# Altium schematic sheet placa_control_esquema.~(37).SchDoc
size A4
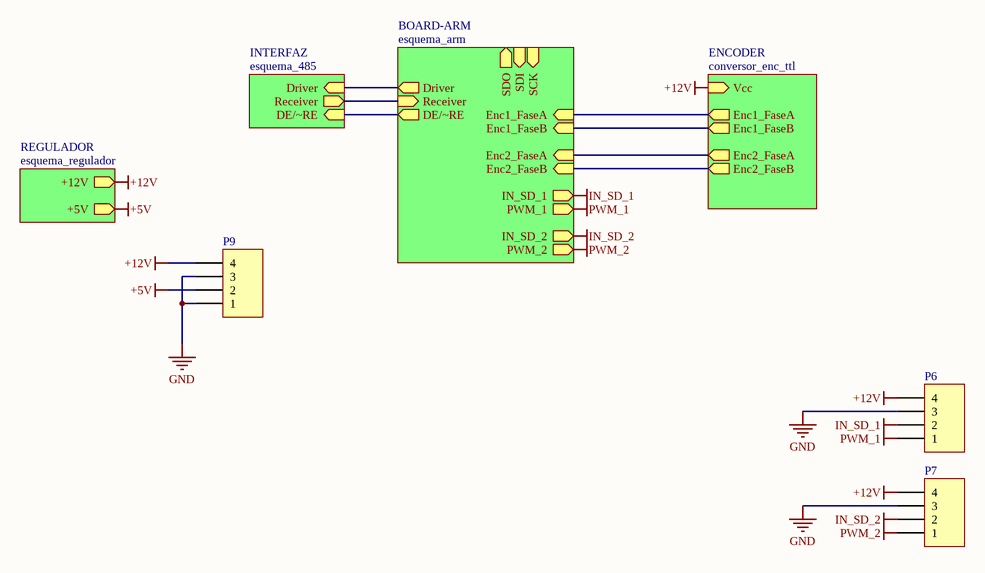
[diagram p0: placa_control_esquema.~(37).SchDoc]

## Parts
P6  Header 4  [HDR1X5]  (value not drawn)
P7  Header 4  [HDR1X5]  (value not drawn)
P9  Header 4  [HDR1X5]  (value not drawn)

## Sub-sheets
BOARD-ARM = esquema_arm: SDI (in), SDO (out), SCK (in), Enc1_FaseA (in), Enc1_FaseB (in), Enc2_FaseA (in), Enc2_FaseB (in), DE/~RE (out), Receiver (in), Driver (out), PWM_1 (out), PWM_2 (out), IN_SD_2 (out), IN_SD_1 (out)
ENCODER = conversor_enc_ttl: Enc1_FaseA (out), Enc1_FaseB (out), Enc2_FaseA (out), Enc2_FaseB (out), Vcc (in)
INTERFAZ = esquema_485: Driver (in), Receiver (out), DE/~RE (in)
REGULADOR = esquema_regulador: +12V (out), +5V (out)

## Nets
+5V: P9.2 ; sheet REGULADOR/+5V
+12V: P6.4 P7.4 P9.4 ; sheet REGULADOR/+12V, sheet ENCODER/Vcc
GND: P6.3 P7.3 P9.1 P9.3
IN_SD_1: P6.2 ; sheet BOARD-ARM/IN_SD_1
IN_SD_2: P7.2 ; sheet BOARD-ARM/IN_SD_2
PWM_1: P6.1 ; sheet BOARD-ARM/PWM_1
PWM_2: P7.1 ; sheet BOARD-ARM/PWM_2
(unnamed): sheet INTERFAZ/Driver, sheet BOARD-ARM/Driver
(unnamed): sheet INTERFAZ/Receiver, sheet BOARD-ARM/Receiver  [a separate net that carries the same name]
(unnamed): sheet INTERFAZ/DE/~RE, sheet BOARD-ARM/DE/~RE  [a separate net that carries the same name]
(unnamed): sheet BOARD-ARM/Enc1_FaseA, sheet ENCODER/Enc1_FaseA  [a separate net that carries the same name]
(unnamed): sheet BOARD-ARM/Enc1_FaseB, sheet ENCODER/Enc1_FaseB  [a separate net that carries the same name]
(unnamed): sheet BOARD-ARM/Enc2_FaseA, sheet ENCODER/Enc2_FaseA  [a separate net that carries the same name]
(unnamed): sheet BOARD-ARM/Enc2_FaseB, sheet ENCODER/Enc2_FaseB  [a separate net that carries the same name]

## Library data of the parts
P6 P7 P9 = Header 4: Header, 4-Pin; value: hdr1x5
